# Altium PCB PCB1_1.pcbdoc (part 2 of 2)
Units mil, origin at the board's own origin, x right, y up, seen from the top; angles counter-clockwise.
Board outline 2550 x 2850 mil, 4 copper layers (Top Layer, GND02, PWR03, Bottom Layer), stack 64.1 mil thick; 130 components, 80 nets, 440 pads, 327 vias.
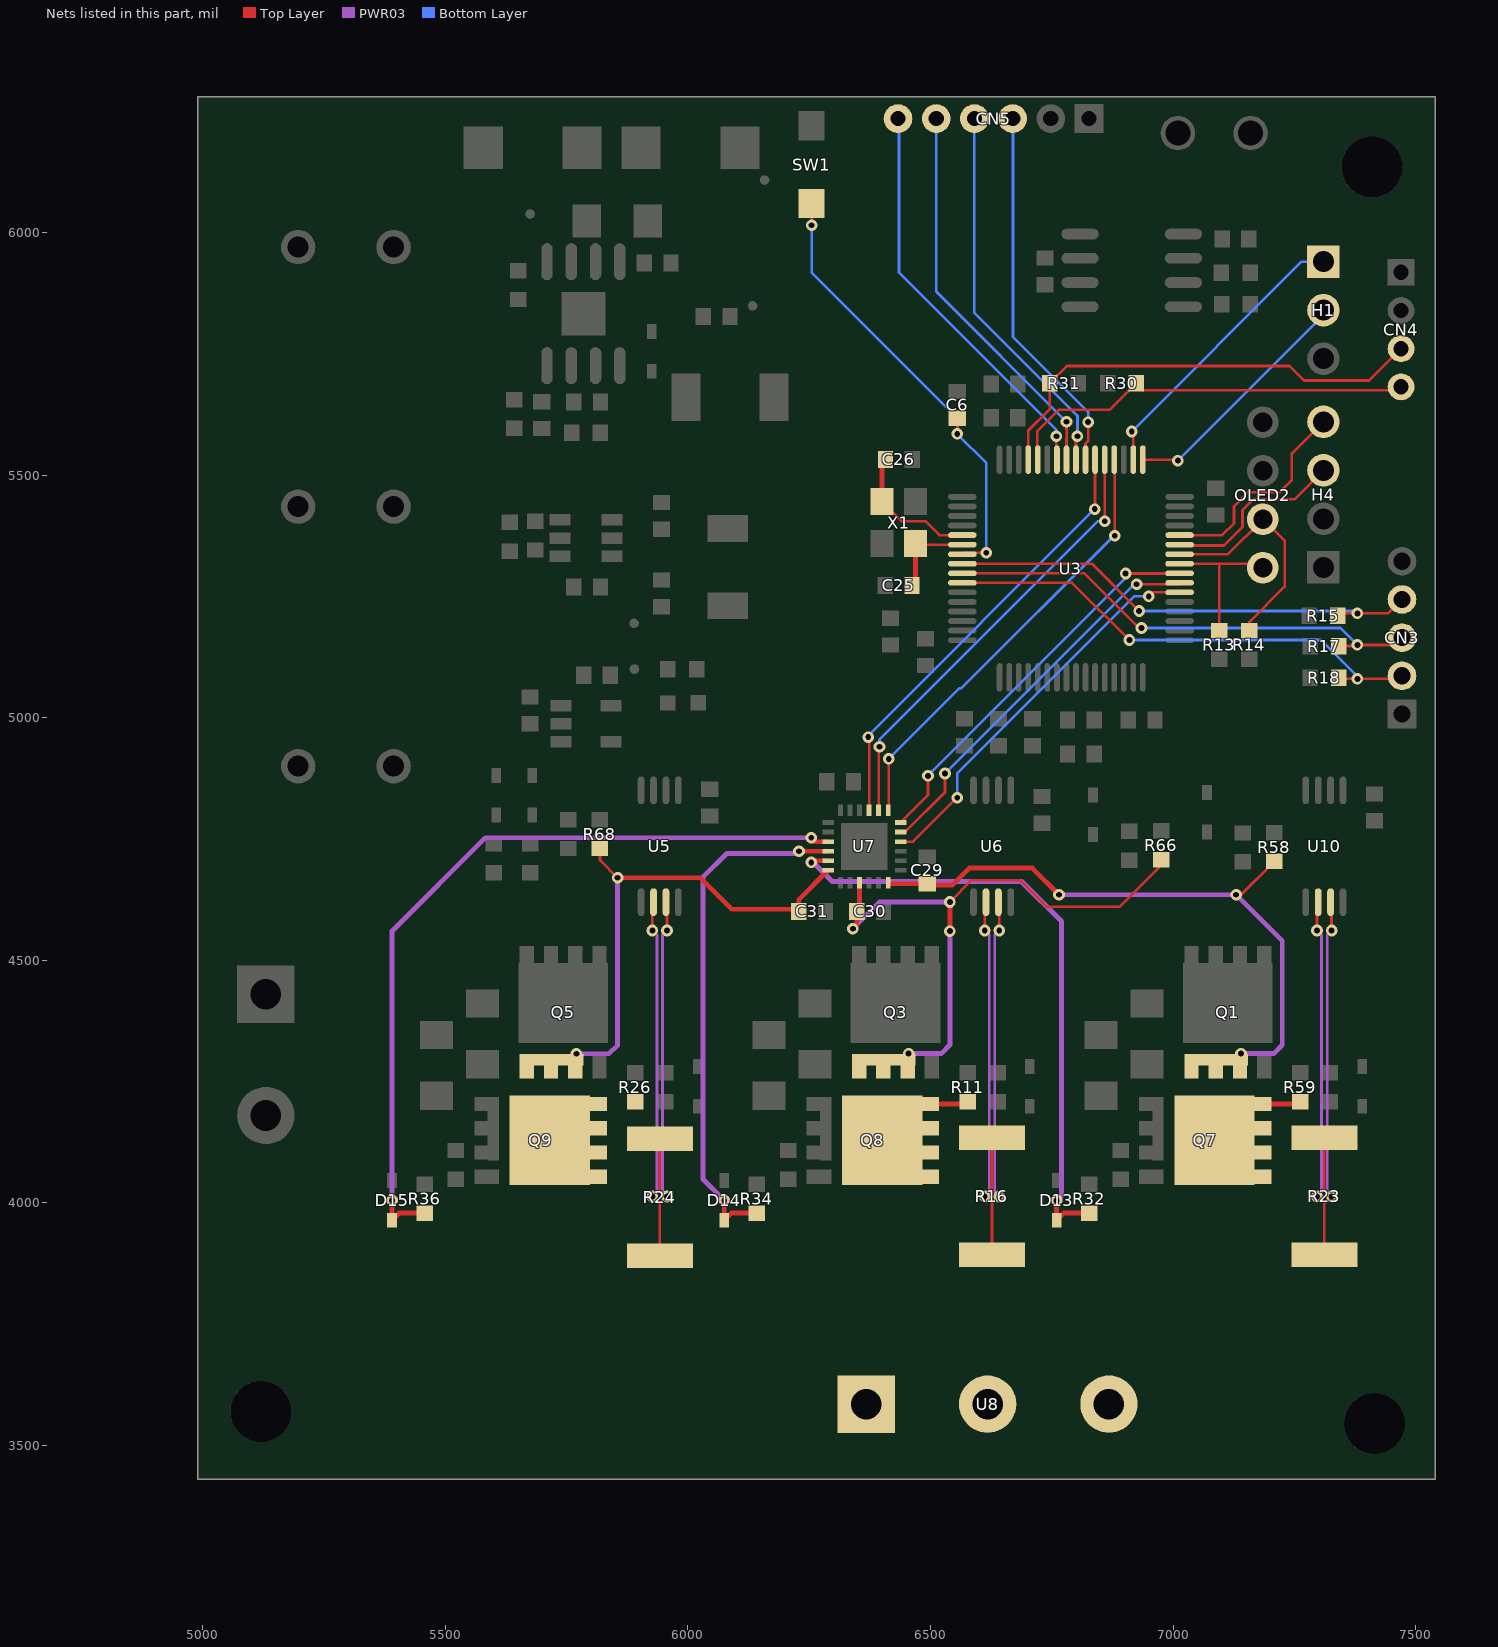
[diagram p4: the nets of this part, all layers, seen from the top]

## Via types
v1: diameter 24, hole 12, Top Layer to Bottom Layer, 327 vias

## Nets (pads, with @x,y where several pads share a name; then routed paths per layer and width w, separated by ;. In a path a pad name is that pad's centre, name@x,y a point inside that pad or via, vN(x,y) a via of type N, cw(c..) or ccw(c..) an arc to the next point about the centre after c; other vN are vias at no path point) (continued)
GLA: D13.2 R32.1 U7.11 | length 1294.7
  Top Layer w10: v1@6254.1,4704.1 6255.1,4705.1 U7.11@6288.8,4705.1 ; v1(6760,4005) D13.2@6760,3964.1 6774.7,3978.8 R32.1@6827.1,3978.8
  PWR03 w10: v1(6254.1,4701.8) 6257.9,4701.8 6297.3,4662.4 6687.6,4662.4 6770,4580 6770,4015 v1(6760,4005)
GLB: D14.2 R34.1 U7.10 | length 1078.5
  Top Layer w10: v1(6075,4005) D14.2@6075,3964.1 6089.7,3978.8 R34.1@6142.1,3978.8 ; v1(6229.1,4724.8) U7.10@6288.8,4724.8
  PWR03 w10: v1(6075,4005) 6030.9,4049.1 6030.9,4670.9 6080,4720 6224.3,4720 v1(6229.1,4724.8)
GLC: D15.2 R36.1 U7.9 | length 1650.9
  Top Layer w10: v1(5390,4005) D15.2@5390,3964.1 5404.7,3978.8 R36.1@5457.1,3978.8 ; v1(6254.1,4752.4) 6262,4744.4 U7.9@6288.8,4744.4
  PWR03 w10: v1(5390,4005) 5390,4560 5582.4,4752.4 v1(6254.1,4752.4)
I2C1_SCL_Encoder&BOOT0: CN4.3 R31.1 U3.61 | length 49.9
  Top Layer w5.5: R31.1@6745.7,5689.7 6781,5725
I2C1_SCL_ENCODER&BOOT0:  | length 904.7
  Top Layer w5.5: 6701.5,5531.9 6701.5,5591.5 6745.7,5635.7 6745.7,5689.7 ; 6781,5725 7240,5725 7270,5695 7404.4,5695 7470,5760.6
I2C1_SDA_Encoder: CN4.4 R30.1 U3.60
I2C1_SDA_ENCODER:  | length 858.9
  Top Layer w5.5: 6721.2,5531.9 6720,5533.1 6720,5590 6765,5635 6869.7,5635 6924.3,5689.7 6939,5675 7463.1,5675 7470,5681.9
I2C3_SCL_OLED: OLED2.3 R14.1 U3.42 | length 479.8
  Top Layer w5.5: U3.42@7013.6,5337 7113.1,5337 OLED2.3@7185.1,5409 7186,5409 7230,5365 7230,5270 7157.4,5197.4 R14.1@7157.4,5179.7
I2C3_SDA_OLED: OLED2.4 R13.1 U3.41 | length 313.2
  Top Layer w5.5: U3.41@7013.6,5317.3 7093.5,5317.3 ; R13.1@7095,5179.7 7095,5315.9 7093.5,5317.3 ; OLED2.4@7185.1,5309 7176.7,5317.3 7093.5,5317.3
IA+: C29.1 Q1.1 Q1.2 Q1.3 Q7.5 Q7.6 Q7.7 Q7.8 R23.1 R58.2 R59.1 U7.18 U10.2 | length 2133.8
  Top Layer w5.5: v1(7130,4635) 7140,4635 R58.2@7208.7,4703.7 ; v1(7296.8,4013.1) 7311.8,4028.1 R23.1@7311.8,4133.8 ; v1(7296.8,4561.4) 7296.8,4617.3 U10.2@7299.2,4619.8
  Top Layer w10: U7.18@6412.8,4659.8 6414.9,4657.8 C29.1@6493.3,4657.8 6496.1,4655 6545,4655 6580,4690 6710,4690 v1(6765,4635) ; Q7.8@7177.2,4203.7 7257,4203.7 R59.1@7261.8,4208.4
  PWR03 w5.5: v1(7296.8,4013.1) 7306.1,4022.5 7306.1,4552.1 v1(7296.8,4561.4)
  PWR03 w10: v1(6765,4635) v1(7130,4635) 7225,4540 7225,4325.2 7207.2,4307.5 v1(7140,4307.5)
IA-: R23.2 U8.3 U10.3 | length 742.1
  Top Layer w5.5: R23.2@7311.8,3892.4 7311.8,3998.1 v1(7326.8,4013.1) ; U10.3@7324.8,4619.8 7326.8,4617.8 v1(7326.8,4561.4)
  PWR03 w5.5: v1(7326.8,4013.1) 7317.6,4022.2 7317.6,4552.3 v1(7326.8,4561.4)
IB+: C30.2 Q3.1 Q3.2 Q3.3 Q8.5 Q8.6 Q8.7 Q8.8 R11.1 R16.1 R66.2 U6.2 U7.15 | length 2063.1
  Top Layer w5.5: v1(6540,4620) 6585,4665 6685,4665 6740,4610 6890,4610 6975.2,4695.2 R66.2@6975.2,4707.1 ; v1(6611.8,4013.1) 6626.8,4028.1 R16.1@6626.8,4133.8 ; v1(6611.8,4561.4) 6611.8,4617.1 U6.2@6614.4,4619.8
  Top Layer w10: v1(6340,4565) 6348.1,4573.1 C30.2@6348.1,4600.5 6353.8,4606.2 U7.15@6353.8,4659.8 ; Q8.8@6492.2,4203.7 6572,4203.7 R11.1@6576.8,4208.4 ; v1(6540,4560) v1(6540,4620)
  PWR03 w5.5: v1(6611.8,4013.1) 6621.1,4022.5 6621.1,4552.1 v1(6611.8,4561.4)
  PWR03 w10: v1(6340,4565) 6395,4620 v1(6540,4620) ; v1(6455,4307.5) 6522.2,4307.5 6540,4325.2 v1(6540,4560)
IB-: R16.2 U6.3 U8.2 | length 742
  Top Layer w5.5: R16.2@6626.8,3892.4 6626.8,3998.1 v1(6641.8,4013.1) ; U6.3@6640,4619.8 6641.8,4618 v1(6641.8,4561.4)
  PWR03 w5.5: v1(6641.8,4013.1) 6632.6,4022.2 6632.6,4552.3 v1(6641.8,4561.4)
IC+: C31.2 Q5.1 Q5.2 Q5.3 Q9.5 Q9.6 Q9.7 Q9.8 R24.1 R26.1 R68.2 U5.2 U7.12 | length 1767
  Top Layer w5.5: R68.2@5818.7,4730.3 5818.7,4706.3 v1(5855,4670) ; v1(5926.8,4013.1) 5941.8,4028.1 R24.1@5941.8,4133.8 ; v1(5926.8,4561.4) 5926.8,4617.4 U5.2@5929.1,4619.8
  Top Layer w10: v1(5855,4670) 6025,4670 6090,4605 6223.8,4605 C31.2@6228.3,4600.5 6228.3,4624.9 U7.12@6288.8,4685.4
  PWR03 w5.5: v1(5926.8,4013.1) 5936.1,4022.5 5936.1,4552.1 v1(5926.8,4561.4)
  PWR03 w10: v1(5770,4307.2) 5837.2,4307.2 5855,4325 v1(5855,4670)
IC-: R24.2 U5.3 U8.1 | length 742.2
  Top Layer w5.5: R24.2@5941.8,3892.4 5941.8,3998.1 v1(5956.8,4013.1) ; U5.3@5954.7,4619.8 5956.8,4617.7 v1(5956.8,4561.4)
  PWR03 w5.5: v1(5956.8,4013.1) 5947.6,4022.2 5947.6,4552.3 v1(5956.8,4561.4)
INHA: U3.38 U7.22 | length 817.4
  Top Layer w5.5: U7.22@6438.4,4744.4 6464.4,4744.4 v1(6555,4835) ; v1(6950,5250) 6958.3,5258.3 U3.38@7013.6,5258.3
  Bottom Layer w5.5: v1(6555,4835) 6555,4885 6920,5250 v1(6950,5250)
INHB: U3.39 U7.23 | length 810.7
  Top Layer w5.5: U7.23@6438.4,4764.1 6447.8,4764.1 6530,4846.3 v1(6530,4885) ; v1(6925,5275) 7010.6,5275 U3.39@7013.6,5278
  Bottom Layer w5.5: v1(6530,4885) 6920,5275 v1(6925,5275)
INHC: U3.40 U7.24 | length 817.1
  Top Layer w5.5: U7.24@6438.4,4783.8 6495,4840.4 v1(6495,4880) ; v1(6902.2,5297.2) 7013.1,5297.2 U3.40@7013.6,5297.7
  Bottom Layer w5.5: v1(6495,4880) 6495,4880.7 6902.2,5287.9 v1(6902.2,5297.2)
INLA: U3.52 U7.1 | length 920.2
  Top Layer w5.5: U7.1@6412.8,4809.4 6413.9,4810.5 v1(6413.9,4915) ; U3.52@6878.7,5531.9 6880,5530.6 v1(6880,5375)
  Bottom Layer w5.5: v1(6413.9,4915) 6559.6,5060.8 6563.6,5060.8 6877.8,5375 v1(6880,5375)
INLB: U3.53 U7.2 | length 924.1
  Top Layer w5.5: U7.2@6393.2,4809.4 6393.2,4938.2 v1(6395,4940) ; U3.53@6859,5531.9 6859.3,5531.7 v1(6859.3,5405)
  Bottom Layer w5.5: v1(6395,4940) 6395,4955 6845,5405 v1(6859.3,5405)
INLC: U3.54 U7.3 | length 916.8
  Top Layer w5.5: v1(6371.8,4960) 6373.5,4958.3 U7.3@6373.5,4809.4 ; v1(6838.5,5430) 6839.3,5430.8 U3.54@6839.3,5531.9
  Bottom Layer w5.5: v1(6371.8,4960) 6371.8,4963.2 v1(6838.5,5430)
PF0-OSC_IN: C26.1 U3.5 X1.1 | length 283.2
  Top Layer w5.5: X1.1@6400.4,5444.6 6440,5405 6490,5405 6518.6,5376.4 U3.5@6565.7,5376.4
  Top Layer w10: X1.1@6400.4,5445.6 6400.4,5525.6 C26.1@6407.2,5532.5
PF1-OSC_OUT: C25.2 U3.6 X1.3 | length 186.9
  Top Layer w5.5: X1.3@6469.3,5359 6471.5,5356.7 U3.6@6565.7,5356.7
  Top Layer w10: C25.2@6462.1,5272.5 6469.3,5279.7 X1.3@6469.3,5359
PG10-NRST: C6.2 SW1.2 U3.7 | length 952.1
  Top Layer w5.5: v1(6255,6015) SW1.2@6255,6060.1 ; v1(6555,5585) C6.2@6555,5617.4 ; U3.7@6565.7,5337 6568.8,5340.1 v1(6615,5340.1)
  Bottom Layer w5.5: v1(6255,6015) 6255,5917.6 6555,5617.6 v1(6555,5585) 6615,5525 v1(6615,5340.1)
SPI1_CS_Encoder: CN5.3 U3.55 | length 689.9
  Bottom Layer w5.5: CN5.3@6670,6235 6670,5785 6825,5630 v1(6825,5609.3)
SPI1_CS_ENCODER:  | length 79.6
  Top Layer w5.5: 6819.6,5531.9 6819.6,5565 6825,5570.4 6825,5609.3
SPI1_MISO_Encoder: CN5.5 U3.57 | length 458
  Top Layer w5.5: U3.57@6780.3,5531.9 6780.3,5575.9 6780.7,5576.4 6780.7,5593.6 6780.3,5594.1 v1(6780.3,5610)
  Bottom Layer w5.5: 6511.9,5878.4 v1(6780.3,5610)
SPI1_MISO_ENCODER:  | length 356.6
  Bottom Layer w5.5: 6511.9,5878.4 6511.9,6235
SPI1_MOSI_Encoder: CN5.6 U3.58 | length 48.6
  Top Layer w5.5: v1(6759.5,5580) 6759.5,5533 U3.58@6760.6,5531.9
SPI1_MOSI_ENCODER:  | length 789.4
  Bottom Layer w5.5: 6435,6235 6435,5917.9 6759.5,5593.4 6759.5,5580
SPI1_SCK_Encoder: CN5.4 U3.56 | length 792.6
  Top Layer w5.5: U3.56@6799.9,5531.9 6799.9,5577.1 v1(6802.9,5580)
  Bottom Layer w5.5: CN5.4@6590,6235 6590,5835 6802.9,5622.1 v1(6802.9,5580)
SPI1_SCK_ENCODER: 
SWCLK: H1.1 U3.50 | length 599.4
  Top Layer w5.5: v1(6915,5590) 6918.1,5586.9 U3.50@6918.1,5531.9
  Bottom Layer w5.5: v1(6915,5590) 7265,5940 H1.1@7310,5940
SWDIO: H1.2 U3.49 | length 507.4
  Top Layer w5.5: U3.49@6937.7,5531.9 7008.1,5531.9 v1(7010,5530)
  Bottom Layer w5.5: v1(7010,5530) 7310,5830 H1.2@7310,5840
TIM1_CH1_Hall_U: CN3.4 R15.1 U3.8 | length 892
  Top Layer w5.5: U3.8@6565.7,5317.3 6832.7,5317.3 v1(6930,5220) ; R15.1@7344.7,5215 v1(7380,5215)
  Bottom Layer w5.5: v1(6930,5220) 7375,5220 v1(7380,5215)
TIM1_CH1_HALL_U:  | length 110.9
  Top Layer w5.5: 7339.7,5210 7344.7,5215 ; 7380,5215 7443.2,5215 7472,5243.7
TIM1_CH2_Hall_V: CN3.3 R17.1 U3.9 | length 914.6
  Top Layer w5.5: U3.9@6565.7,5297.7 6817.3,5297.7 6930,5185 v1(6935,5185) ; R17.1@7341.8,5147.7 7377.7,5147.7 v1(7380,5150)
  Bottom Layer w5.5: v1(6935,5185) 7345,5185 v1(7380,5150)
TIM1_CH2_HALL_V:  | length 98.2
  Top Layer w5.5: 7380,5150 7457,5150 7472,5165
TIM1_CH3_Hall_W: CN3.2 R18.1 U3.10 | length 940.8
  Top Layer w5.5: U3.10@6565.7,5278 6792,5278 v1(6910,5160) ; R18.1@7341.6,5082.7 7344.3,5080 v1(7380,5080)
  Bottom Layer w5.5: v1(6910,5160) 7305,5160 v1@7385,5080
TIM1_CH3_HALL_W:  | length 89.6
  Top Layer w5.5: 7385,5080 7465.7,5080 7472,5086.3
USART1_RX: H4.4 U3.44 | length 445.9
  Top Layer w5.5: U3.44@7013.6,5376.4 7101.4,5376.4 7125.7,5400.7 7125.7,5435.7 7155,5465 7220,5465 7245,5490 7245,5545 H4.4@7310,5610
USART1_TX: H4.3 U3.43 | length 360.3
  Top Layer w5.5: U3.43@7034.9,5353.8 7036.1,5355 7105,5355 7143.1,5393.1 7143.1,5428.1 7165.2,5450.2 7250.2,5450.2 H4.3@7310,5510
pads on no net: U3.2 U3.3 U3.4 U3.11 U3.21 U3.22 U3.23 U3.24 U3.25 U3.26 U3.30 U3.33 U3.34 U3.35 U3.36 U3.37 U3.51 U3.59 U3.62 U4.4 U5.1 U6.1 U7.5 U7.7 U7.8 U7.21 U10.1 U18.5

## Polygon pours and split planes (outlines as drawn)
AGND on Bottom Layer (solid, remove dead copper, pour order 2): 4580,6575 4580,3075 8170,3075 8170,6575
AGND on Top Layer (solid, remove dead copper, pour order 2): 4495,6820 4495,4580 7725,4580 7725,6820
3.3V on PWR03 (solid, remove dead copper): 5655,4920 5835,5100 6408.7,5100 6564.6,5255.9 6564.6,5609.6 6630,5675 6925,5675 7135,5465 7135,5075 7305,4905 7465,4905 7480,4890 7480,4850 7455,4825 5694.3,4825 5655,4864.3
AGND on PWR03 (solid, remove dead copper): 8110,6275 8110,4915 7780,4585 5660,4585 5660,4865 5697,4828 7453,4828 7476.5,4851.5 7476.5,4888.5 7465,4900 7304.2,4900 7131.6,5072.7 7131.6,5468.4 6925,5675 6635,5675 6567.1,5607.1 6567.1,5258.3 6408.8,5100 5835,5100 5655.3,4920.4 5655.3,6710.3 5750,6805 8065,6805 8185,6685 8185,6350
AGND on PWR03 (solid, remove dead copper): 3000,7160 3000,4585 5660,4585 5660,7160
AGND on PWR03 (solid, remove dead copper): 5024.9,4589.9 5024.9,4034.1 5390,4034.1 5390,4589.9

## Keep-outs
PWR03:
  region: 6369.8,5312.3 6368.7,5313.4 6368.7,5492.3 6499.8,5492.3 6499.8,5312.3
  region: 6040,4655 6040,4570 6715,4570 6715,4655
Bottom Layer:
  region: 6369.8,5312.3 6368.7,5313.4 6368.7,5492.3 6499.8,5492.3 6499.8,5312.3
GND02:
  region: 5831.6,6040.7 5822.9,6040.7 5822.9,6027.2 5831.6,6027.2
  region: 5831.7,6013.8 5822.3,6013.8 5822.3,5998.7 5831.7,5998.7
  region: 6369.8,5312.3 6368.7,5313.4 6368.7,5492.3 6499.8,5492.3 6499.8,5312.3
  region: 6770.9,5594.1 6770.9,5576.4 6791.4,5576.4 6791.4,5594.1
  region: 6442.6,6274.4 6442.6,6235 6815,6235 6815,6274.4
  region: 6763.5,6274.4 6763.5,6235 6805,6235 6805,6274.4
Board Outline Layer:
  region: 6197,5763.2 5976.6,5763.2 5976.6,5558.5 6197,5558.5
  region: 5996.6,5220.7 6167.9,5220.7 6167.9,5399.9 5996.6,5399.9
  lines w10: 4990,3430 4990,6280 7540,6280 7540,3430 4990,3430

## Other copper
Top Layer:
  drawing of 467 lines, arcs and shapes, not listed
PWR03:
  region net IA+: 7304.2,4024.4 7308.1,4020.5 7307.7,4019.8 7307.6,4018.8 7307.9,4016.5 7308.5,4014.1 7308.7,4012.4 7296,4025.1 7297.8,4024.8 7300.1,4024.2 7302.5,4023.9 7303.5,4024
  region net IA-: 7315.7,4020.3 7319.6,4024.2 7320.2,4023.8 7321.2,4023.7 7323.5,4024.1 7325.8,4024.8 7327.5,4025.1 7314.8,4012.4 7315.1,4014.1 7315.7,4016.4 7316.1,4018.7 7316,4019.6
  region net IA+: 7308.1,4554 7304.2,4550.1 7303.5,4550.5 7302.5,4550.6 7300.1,4550.3 7297.8,4549.7 7296,4549.4 7308.7,4562.2 7308.5,4560.4 7307.9,4558 7307.6,4555.7 7307.7,4554.7
  region net IA-: 7319.6,4550.3 7315.7,4554.2 7316,4554.9 7316.1,4555.8 7315.7,4558.1 7315.1,4560.5 7314.8,4562.2 7327.5,4549.4 7325.8,4549.7 7323.5,4550.4 7321.2,4550.8 7320.2,4550.7
  region net IB+: 6623.1,4554 6619.2,4550.1 6618.5,4550.5 6617.5,4550.6 6615.1,4550.3 6612.8,4549.7 6611,4549.4 6623.7,4562.2 6623.5,4560.4 6622.9,4558 6622.6,4555.7 6622.7,4554.7
  region net IB-: 6630.7,4020.3 6634.6,4024.2 6635.2,4023.8 6636.2,4023.7 6638.5,4024.1 6640.8,4024.8 6642.5,4025.1 6629.8,4012.4 6630.1,4014.1 6630.7,4016.4 6631.1,4018.7 6631,4019.6
  region net IB-: 6634.6,4550.3 6630.7,4554.2 6631,4554.9 6631.1,4555.8 6630.7,4558.1 6630.1,4560.5 6629.8,4562.2 6642.5,4549.4 6640.8,4549.7 6638.5,4550.4 6636.2,4550.8 6635.2,4550.7
  region net IC+: 5938.1,4554 5934.2,4550.1 5933.5,4550.5 5932.5,4550.6 5930.1,4550.3 5927.8,4549.7 5926,4549.4 5938.7,4562.2 5938.5,4560.4 5937.9,4558 5937.6,4555.7 5937.7,4554.7
  region net IC-: 5949.6,4550.3 5945.7,4554.2 5946,4554.9 5946.1,4555.8 5945.7,4558.1 5945.1,4560.5 5944.8,4562.2 5957.5,4549.4 5955.8,4549.7 5953.5,4550.4 5951.2,4550.8 5950.2,4550.7
  region net IC+: 5934.2,4024.4 5938.1,4020.5 5937.7,4019.8 5937.6,4018.8 5937.9,4016.5 5938.5,4014.1 5938.7,4012.4 5926,4025.1 5927.8,4024.8 5930.1,4024.2 5932.5,4023.9 5933.5,4024
  region net GLC: 5385,4021.3 5395,4021.3 5395.3,4019.5 5396.3,4017.3 5397.5,4014.9 5399,4012.9 5381,4012.9 5382.5,4014.9 5383.8,4017.3 5384.7,4019.5
  region net GHC: 6048.9,4325.6 6058.9,4325.6 6059.2,4323.8 6060.1,4321.5 6061.4,4319.2 6062.9,4317.2 6044.9,4317.2 6046.3,4319.2 6047.6,4321.5 6048.5,4323.8
  region net GHC: 6270.4,4635 6265.7,4645 6266.7,4645.1 6267.9,4645.4 6270.3,4646.5 6272.5,4648 6273.4,4648.9 6274.1,4649.7 6278.8,4632.4 6276.6,4633.3 6274.2,4634.2 6272,4634.8
  region net GLB: 6217,4715 6209.8,4725 6211,4725.1 6212.3,4725.4 6214.7,4726.5 6215.9,4727.3 6216.9,4728.1 6217.7,4729 6218.2,4729.9 6225.4,4713.4 6220.9,4714.5 6218.6,4714.9
  region net GHB: 6736.1,4325.5 6746.1,4325.5 6746.4,4323.7 6747.3,4321.4 6748.6,4319.1 6750.1,4317.1 6732.1,4317.1 6733.6,4319.1 6734.8,4321.4 6735.7,4323.7
  region net GHB: 6383,4579.9 6390.1,4572.8 6389.1,4571.3 6388.1,4569.1 6387.4,4566.5 6387,4564.1 6374.2,4576.8 6376.7,4577.2 6379.3,4577.9 6381.5,4578.9
  region net GLA: 6269.5,4697.3 6265.3,4687.3 6264.5,4688 6263.5,4688.6 6261.1,4689.5 6258.5,4690 6257.2,4690 6256.1,4689.9 6265.6,4705.2 6266.4,4702.9 6267.5,4700.6 6268.6,4698.6
  region net GLB: 6059.9,4013 6067,4020.1 6068.5,4019.1 6070.7,4018.1 6073.3,4017.4 6075.8,4017 6063,4004.2 6062.6,4006.7 6061.9,4009.3 6060.9,4011.5
  region net GLA: 6766.5,4018.5 6773.5,4011.5 6773.1,4010.5 6772.6,4008.8 6772.2,4006.6 6772,4004.2 6759.2,4017 6761.6,4017.2 6763.8,4017.6 6765.5,4018.1
  region net IC+: 5786.3,4312.2 5786.3,4302.2 5784.5,4301.9 5782.3,4301 5779.9,4299.7 5777.9,4298.2 5777.9,4316.2 5779.9,4314.8 5782.3,4313.5 5784.5,4312.6
  region net IC+: 5860,4653.7 5850,4653.7 5849.7,4655.5 5848.8,4657.7 5847.5,4660.1 5846,4662.1 5864,4662.1 5862.5,4660.1 5861.3,4657.7 5860.3,4655.5
  region net IA+: 7156.3,4312.5 7156.3,4302.5 7154.5,4302.1 7152.3,4301.2 7149.9,4299.9 7147.9,4298.5 7147.9,4316.5 7149.9,4315 7152.3,4313.7 7154.5,4312.8
  region net IB+: 6471.3,4312.5 6471.3,4302.5 6469.5,4302.1 6467.3,4301.2 6464.9,4299.9 6462.9,4298.5 6462.9,4316.5 6464.9,4315 6467.3,4313.7 6469.5,4312.8
  region net IB+: 6348,4580.1 6355.1,4573 6354.1,4571.5 6353.1,4569.3 6352.4,4566.7 6352,4564.2 6339.2,4577 6341.7,4577.4 6344.3,4578.1 6346.5,4579.1
  region net IB+: 6523.7,4615 6523.7,4625 6525.5,4625.3 6527.7,4626.3 6530.1,4627.5 6532.1,4629 6532.1,4611 6530.1,4612.5 6527.7,4613.8 6525.5,4614.7
  region net IB+: 6545,4543.7 6535,4543.7 6534.7,4545.5 6533.8,4547.7 6532.5,4550.1 6531,4552.1 6549,4552.1 6547.5,4550.1 6546.3,4547.7 6545.3,4545.5
  region net GHA: 7385,4256.3 7395,4256.3 7395.3,4254.5 7396.3,4252.3 7397.5,4249.9 7399,4247.9 7381,4247.9 7382.5,4249.9 7383.8,4252.3 7384.7,4254.5
  region net GHA: 6545.7,4690 6545.1,4680 6543.4,4679.7 6541.1,4678.8 6538.8,4677.6 6536.7,4676.1 6537.3,4694.1 6539.3,4692.6 6541.6,4691.3 6543.9,4690.4
  region net IA+: 6781.3,4640 6781.3,4630 6779.5,4629.7 6777.3,4628.8 6774.9,4627.5 6772.9,4626 6772.9,4644 6774.9,4642.5 6777.3,4641.3 6779.5,4640.3
  region net GLC: 6237.8,4747.4 6237.8,4757.4 6239.6,4757.7 6241.8,4758.6 6244.2,4759.9 6246.2,4761.4 6246.2,4743.4 6244.2,4744.8 6241.8,4746.1 6239.6,4747
  region net IA+: 7113.7,4630 7113.7,4640 7115.5,4640.3 7117.7,4641.3 7120.1,4642.5 7122.1,4644 7122.1,4626 7120.1,4627.5 7117.7,4628.8 7115.5,4629.7
  region net IA+: 7145.1,4627 7138,4619.9 7136.5,4620.9 7134.3,4621.9 7131.7,4622.6 7129.2,4623 7142,4635.8 7142.4,4633.3 7143.1,4630.7 7144.1,4628.5
Bottom Layer:
  region net AGND: 5934.2,5295.2 5930.3,5299.1 5930.7,5300.3 5931.2,5302.7 5931.9,5309.5 5944.6,5296.8 5937.8,5296.1 5935.4,5295.6
  region net $1N197: 5836.1,5274.6 5836.1,5264.6 5834.3,5264.3 5832.1,5263.4 5829.7,5262.1 5827.7,5260.6 5827.7,5278.6 5829.7,5277.2 5832.1,5275.9 5834.3,5275
  region net $1N197: 5885,5356.9 5875,5356.6 5874.7,5358.5 5873.7,5360.7 5872.4,5363.1 5871,5365 5888.9,5365.3 5887.5,5363.2 5886.2,5360.9 5885.3,5358.7
  region net $1N197: 5867.9,5356.9 5865.6,5359.2 5865.6,5385.4 5890.1,5410 6070,5410 6070,5373.3 5904.7,5373.3 5888.3,5356.9
  region net 5V: 5895.9,5219.2 5897.1,5224.7 5900,5226.6 5905.5,5230.7 5904.3,5212.7 5901.8,5215.1 5899.3,5217.2 5897.2,5218.7
  region net 5V: 5651.3,5303.8 5647.4,5299.9 5646.3,5300.3 5643.8,5300.8 5637.1,5301.5 5649.8,5314.2 5650.5,5307.4 5650.9,5305
  region net AGND: 5698.1,5302.1 5692.3,5300.2 5691.2,5300.9 5690,5301.4 5688.6,5301.7 5687.2,5301.9 5684.4,5302 5682.4,5302.2 5696.9,5312.9 5696.8,5309.5 5697,5306.2 5697.4,5303.6 5697.7,5302.7
  region net 12V: 5899.8,5448.6 5903.9,5454.1 5905.2,5454.3 5906.4,5454.8 5907.6,5455.5 5908.7,5456.3 5910.8,5458 5912.3,5459.2 5908.2,5441.7 5906.1,5444.2 5903.7,5446.5 5901.5,5448 5900.5,5448.5
  region net 12V: 5768.6,5385.6 5774.1,5385.6 5774.7,5384.5 5776.1,5382.5 5780.4,5377.2 5762.4,5377.2 5766.7,5382.5 5768.1,5384.5
  region net ADC_CU: 6586.3,5042.8 6586.3,5037.3 6585.2,5036.7 6583.2,5035.3 6577.9,5031 6577.9,5049 6583.2,5044.7 6585.2,5043.3
  region net ADC_CU: 6608.7,5037.3 6608.7,5042.8 6609.8,5043.3 6611.8,5044.7 6617.1,5049 6617.1,5031 6611.8,5035.3 6609.8,5036.7
  region net ADC_AU: 6758.1,4959.7 6754.2,4955.8 6753.1,4956.2 6750.6,4956.6 6743.9,4957.3 6756.6,4970 6757.3,4963.3 6757.7,4960.8
  region net ADC_AU: 7029.8,4786.3 7033.7,4790.2 7034.8,4789.8 7037.3,4789.4 7044,4788.7 7031.3,4776 7030.6,4782.7 7030.2,4785.2
  region net $1N188: 5945,5883.7 5935,5883.7 5934.7,5885.5 5933.8,5887.7 5932.5,5890.1 5931,5892.1 5949,5892.1 5947.5,5890.1 5946.3,5887.7 5945.3,5885.5
  region net $1N188: 5902.5,5730.8 5909.6,5723.7 5908.6,5722.2 5907.6,5720 5906.9,5717.4 5906.5,5715 5893.8,5727.7 5896.2,5728.1 5898.8,5728.8 5901,5729.8
  region net 12V: 6124.2,5821.3 6126.9,5815.8 6126.2,5815.6 6125.4,5815.2 6123.2,5813.7 6120.8,5811.5 6118.5,5809 6115.8,5826.8 6117.3,5825.5 6119.4,5823.6 6120.5,5822.8 6121.7,5822 6122.9,5821.5
  region net 12V: 5711.9,5545 5700.4,5548.7 5699.5,5549.5 5698.5,5550.2 5696.3,5551.4 5694.4,5552.3 5693,5553.1 5710.5,5555.5 5709.9,5554.4 5709.6,5553.1 5709.5,5551.7 5709.6,5550.2 5709.8,5548.8 5710.3,5547.4 5711,5546.1
  region net INLA: 6868.5,5361.8 6866.3,5367.3 6868.2,5377.3 6879.2,5363 6875.8,5363.1 6872.5,5362.9 6870,5362.4 6869.1,5362.1
  region net INLA: 6423.5,4928.5 6427.4,4924.6 6427,4923.5 6426.6,4921 6425.9,4914.2 6413.1,4927 6419.9,4927.7 6422.3,4928.1
  region net INHA: 6552.3,4851.3 6557.8,4851.3 6558.3,4850.2 6559.7,4848.2 6564,4842.9 6546,4842.9 6550.3,4848.2 6551.7,4850.2
  region net INHA: 6933.7,5247.3 6933.7,5252.8 6934.8,5253.3 6936.8,5254.7 6942.1,5259 6942.1,5241 6936.8,5245.3 6934.8,5246.7
  region net INHC: 6504,4893.6 6508.4,4890.2 6508,4888.9 6507.5,4886.5 6507.2,4883.2 6507,4879.7 6493.8,4891.9 6500.6,4892.8 6503,4893.2
  region net INHC: 6901.7,5283.5 6890.8,5280.3 6891.6,5281.3 6892.2,5282.6 6892.6,5284 6892.8,5285.5 6892.9,5287 6892.7,5288.5 6892.4,5290 6891.8,5291.2 6909.4,5287.6 6908,5286.9 6905.9,5286 6903.7,5285 6902.7,5284.3
  region net INHB: 6911.3,5262.4 6911.1,5270 6911.9,5271 6912.4,5272.2 6912.8,5273.5 6913.1,5274.8 6913.4,5277.4 6913.8,5279.2 6922.2,5263.3 6919,5263.8 6915.8,5263.8 6913,5263.3 6912,5262.9
  region net INHB: 6539.6,4898.5 6543.5,4894.6 6543.1,4893.5 6542.7,4891 6542,4884.2 6529.2,4897 6536,4897.7 6538.5,4898.1
  region net INLC: 6828.9,5416.5 6825,5420.4 6825.4,5421.5 6825.9,5424 6826.6,5430.8 6839.3,5418 6832.5,5417.3 6830.1,5416.9
  region net INLC: 6378.4,4973.8 6384.8,4972.3 6384.4,4971.7 6384,4970.8 6383.6,4968.1 6383.4,4964.9 6383.7,4961.5 6368.7,4971.6 6370.7,4971.8 6373.4,4972 6374.8,4972.2 6376.2,4972.5 6377.4,4973
  region net TIM1_CH1_HALL_U: 6946.3,5222.8 6946.3,5217.3 6945.2,5216.7 6943.2,5215.3 6937.9,5211 6937.9,5229 6943.2,5224.7 6945.2,5223.3
  region net TIM1_CH1_HALL_U: 7360.6,5217.3 7368.1,5222.8 7369.4,5222.9 7370.6,5223.3 7372.9,5224.4 7375,5225.7 7376.5,5226.5 7369,5210.1 7368.3,5211.5 7367.4,5212.7 7366.4,5213.9 7365.2,5215 7364,5215.9 7362.8,5216.6 7361.7,5217.1
  region net TIM1_CH2_HALL_V: 6951.3,5187.8 6951.3,5182.3 6950.2,5181.7 6948.2,5180.3 6942.9,5176 6942.9,5194 6948.2,5189.7 6950.2,5188.3
  region net TIM1_CH2_HALL_V: 7366.5,5159.6 7370.4,5163.5 7371.5,5163.1 7374,5162.7 7380.8,5162 7368,5149.2 7367.3,5156 7366.9,5158.5
  region net TIM1_CH3_HALL_W: 6926.3,5162.8 6926.3,5157.3 6925.2,5156.7 6923.2,5155.3 6917.9,5151 6917.9,5169 6923.2,5164.7 6925.2,5163.3
  region net TIM1_CH3_HALL_W: 7367.4,5093.7 7375,5093.9 7376,5093.1 7377.2,5092.6 7378.5,5092.2 7379.8,5091.9 7382.4,5091.6 7384.2,5091.2 7368.3,5082.8 7368.8,5086 7368.8,5089.2 7368.3,5092 7367.9,5093
  region net 12V: 6314.9,4908 6322,4915.1 6323.5,4914.1 6325.7,4913.1 6328.3,4912.4 6330.8,4912 6318,4899.2 6317.6,4901.7 6316.9,4904.3 6315.9,4906.5
  region net 12V: 6195.1,5442 6188,5434.9 6186.5,5435.9 6184.3,5436.9 6181.7,5437.6 6179.2,5438 6192,5450.8 6192.4,5448.3 6193.1,5445.7 6194.1,5443.5
  region net SPI1_MOSI_ENCODER: 6756.8,5593.4 6762.3,5593.4 6762.5,5592.6 6763.1,5591.8 6765,5590.3 6767.1,5589 6768.5,5587.9 6750.5,5587.9 6752,5589 6754.1,5590.3 6756,5591.8 6756.6,5592.6
  region net SPI1_MOSI_ENCODER: 6437.8,6196.2 6432.3,6193.5 6430.5,6195.4 6426,6200.2 6412.3,6214.1 6456.5,6216.9 6454.7,6215.1 6452.1,6213 6445.8,6208 6442.8,6205.2 6440.2,6202.3 6439.2,6200.8 6438.4,6199.3 6437.9,6197.8
  region net SPI1_MISO_ENCODER: 6766.8,5619.6 6770.6,5623.5 6771.8,5623.1 6774.2,5622.7 6781,5622 6768.3,5609.3 6767.6,5616 6767.1,5618.5
  region net SPI1_MISO_ENCODER: 6514.6,6194.8 6509.1,6194.8 6509,6196.3 6508.5,6197.9 6507.7,6199.4 6506.6,6200.9 6505.4,6202.4 6504,6203.9 6500.8,6206.6 6494.4,6211.6 6491.7,6213.7 6489.7,6215.5 6534,6215.5 6532.1,6213.7 6529.4,6211.6 6522.9,6206.6 6519.8,6203.9 6518.4,6202.4 6517.1,6200.9 6516.1,6199.4 6515.3,6197.9 6514.8,6196.3
  region net SPI1_SCK_ENCODER: 6800.1,5596.3 6805.6,5596.3 6806.2,5595.2 6807.6,5593.2 6811.9,5587.9 6793.9,5587.9 6798.2,5593.2 6799.6,5595.2
  region net SPI1_SCK_ENCODER: 6592.8,6194.3 6587.3,6195.3 6587.1,6196.8 6586.6,6198.4 6585.8,6199.9 6584.8,6201.4 6583.5,6202.9 6582.1,6204.3 6579,6207.1 6572.6,6212.1 6569.9,6214.2 6568.1,6215.9 6612.4,6215 6610.4,6213.2 6607.7,6211.2 6604.5,6208.8 6601.1,6206.2 6597.9,6203.4 6596.5,6201.9 6595.3,6200.5 6594.2,6199 6593.4,6197.4 6592.9,6195.9
  region net SPI1_CS_ENCODER: 6822.3,5625.6 6827.8,5625.6 6828.3,5624.5 6829.7,5622.5 6834,5617.2 6816,5617.2 6820.3,5622.5 6821.7,5624.5
  region net SPI1_CS_ENCODER: 6672.8,6195.3 6667.3,6194.3 6667.1,6195.9 6666.6,6197.4 6665.8,6199 6664.7,6200.5 6663.5,6201.9 6662.1,6203.4 6658.9,6206.2 6655.5,6208.8 6652.3,6211.2 6649.6,6213.2 6647.6,6215 6691.9,6215.9 6690.1,6214.2 6687.4,6212.1 6681,6207.1 6677.9,6204.3 6676.5,6202.9 6675.2,6201.4 6674.2,6199.9 6673.4,6198.4 6672.9,6196.8
  region net PG10-NRST: 6612.3,5356.5 6617.8,5356.5 6618.3,5355.4 6619.7,5353.3 6624,5348.1 6606,5348.1 6610.3,5353.3 6611.7,5355.4
  region net PG10-NRST: 6568.5,5575.4 6564.6,5571.5 6563.5,5571.9 6561,5572.3 6554.2,5573 6567,5585.8 6567.7,5579 6568.1,5576.5
  region net SWDIO: 7019.6,5543.5 7023.5,5539.6 7023.1,5538.5 7022.7,5536 7022,5529.2 7009.2,5542 7016,5542.7 7018.5,5543.1
  region net SWDIO: 7288.8,5804.9 7277.4,5801.3 7277.8,5801.9 7278.1,5802.7 7278.5,5805.3 7278.7,5808.9 7278.8,5813.3 7278.6,5818.3 7278.2,5823.7 7277.7,5829.4 7276.9,5835 7319.1,5807.8 7317.9,5807.6 7316.4,5807.5 7312.8,5807.6 7304.3,5808.2 7299.8,5808.3 7297.6,5808.2 7295.5,5808 7293.6,5807.5 7291.8,5806.9 7290.2,5806
  region net SWCLK: 6924.6,5603.5 6928.5,5599.6 6928.1,5598.5 6927.7,5596 6927,5589.2 6914.2,5602 6921,5602.7 6923.5,5603.1
  region net SWCLK: 7268.3,5937.3 7268.3,5942.8 7270.7,5943 7272.9,5943.8 7274.9,5945.1 7276.5,5946.9 7276.5,5933.1 7274.9,5934.9 7272.9,5936.2 7270.7,5937 7268.3,5937.3
  region net FDCAN1_RX: 6898.3,5482.9 6903.8,5482.9 6904.4,5481.8 6905.8,5479.8 6910.1,5474.5 6892.1,5474.5 6896.4,5479.8 6897.8,5481.8
  region net FDCAN1_RX: 7155.7,5746.9 7156.1,5755 7156.9,5756 7157.5,5757.2 7158.2,5759.8 7158.5,5762.2 7159,5764 7166.7,5747.8 7165.2,5748.1 7163.6,5748.3 7160.4,5748.3 7158.9,5748.1 7157.6,5747.8 7156.5,5747.4
  region net FDCAN1_TX: 6935,5493.9 6942.6,5493.7 6942.1,5493 6941.7,5492 6941.2,5489.2 6941.2,5486 6941.7,5482.8 6925.8,5491.2 6927.6,5491.6 6930.2,5491.9 6931.5,5492.2 6932.8,5492.6 6934,5493.1
  region net FDCAN1_TX: 7222.8,5775 7217.3,5775 7217,5776.1 7216.4,5777.1 7215.6,5778.1 7214.6,5779.1 7212.5,5780.8 7211,5782.1 7229,5782.1 7227.5,5780.8 7225.4,5779.1 7224.4,5778.1 7223.6,5777.1 7223,5776.1
  region net PG10-NRST: 6552.3,5601.3 6557.8,5601.3 6558.3,5600.2 6559.7,5598.2 6564,5592.9 6546,5592.9 6550.3,5598.2 6551.7,5600.2
  region net PG10-NRST: 6257.8,5998.7 6252.3,5998.7 6251.7,5999.8 6250.3,6001.8 6246,6007.1 6264,6007.1 6259.7,6001.8 6258.3,5999.8
  region net 5V: 7440,5347.4 7447.1,5354.4 7449.6,5354 7455.8,5353.3 7473.8,5351.9 7442.5,5320.6 7441.1,5338.7 7440.5,5344.8
  region net 5V: 7212.8,5543.8 7219.9,5536.7 7219.5,5534 7218.9,5527.2 7217.5,5507 7183,5541.4 7203.3,5542.9 7210.1,5543.5
  region net 5V: 7410,5924.9 7404.6,5925.1 7399.4,5926 7394.2,5927.4 7389.2,5929.4 7384.5,5931.9 7380,5934.9 7375,5919.9 7380,5904.9 7384.5,5907.8 7389.2,5910.3 7394.2,5912.3 7399.4,5913.7 7404.6,5914.6 7410,5914.9
  region net 5V: 7427.4,5914.9 7427.4,5924.9 7430.9,5925.2 7434.2,5926.1 7437.3,5927.7 7440.1,5929.8 7442.4,5932.4 7442.4,5907.4 7440.1,5909.9 7437.3,5912 7434.2,5913.6 7430.9,5914.5 7427.4,5914.9
  region net 5V: 7340,5557.2 7345.4,5556.9 7350.6,5556 7355.8,5554.6 7360.8,5552.6 7365.5,5550.2 7370,5547.2 7375,5562.2 7370,5577.2 7365.5,5574.2 7360.8,5571.7 7355.8,5569.7 7350.6,5568.3 7345.4,5567.5 7340,5567.2
  region net 5V: 6821.9,6100 6821.6,6094.6 6820.7,6089.3 6819.3,6084.2 6817.3,6079.2 6814.8,6074.4 6811.8,6070 6811.9,6070 6826.5,6065 6841.9,6070 6841.8,6070 6838.9,6074.4 6836.4,6079.2 6834.4,6084.2 6833,6089.3 6832.1,6094.6 6831.9,6100 6821.9,6100
  region net 5V: 6831.9,6190.5 6821.9,6190.5 6821.5,6193.9 6820.6,6197.3 6819,6200.4 6816.9,6203.1 6814.4,6205.5 6839.4,6205.5 6836.8,6203.1 6834.7,6200.4 6833.1,6197.3 6832.2,6193.9 6831.9,6190.5
  region net 5V: 6781.3,6070 6781.3,6060 6779.5,6059.6 6777.2,6058.7 6774.9,6057.5 6772.9,6056 6772.9,6074 6774.9,6072.5 6777.2,6071.2 6779.5,6070.3
  region net INLB: 6392.3,4955 6397.8,4955 6398,4953.9 6398.6,4952.9 6399.4,4951.9 6400.4,4950.9 6402.5,4949.2 6404,4947.9 6386,4947.9 6387.5,4949.2 6389.6,4950.9 6390.6,4951.9 6391.4,4952.9 6392,4953.9
  region net INLB: 6845,5402.3 6845,5407.8 6845.9,5408 6846.9,5408.6 6847.8,5409.4 6848.6,5410.4 6850.1,5412.5 6851.3,5414 6851.3,5396 6850.1,5397.5 6848.6,5399.6 6847.8,5400.6 6846.9,5401.4 6845.9,5402

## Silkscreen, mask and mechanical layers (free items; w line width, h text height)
Top Silkscreen Layer:
  drawing of 13 lines, arcs and shapes, not listed
  text "GND" at 6135,6035 h39.4
  text "SPI" at 6475,5995 h120
  text "DCBUS" at 5595,5985 h39.4
  text "12V" at 6155.9,5875.3 h39.4
  text "SW" at 7070,5690 h120
  text "I2C" at 7370,5455 h120
  text "5V" at 5810,5180 h39.4
  text "3.3V" at 5785,5125 h39.4
  text "PWR" at 5945,4955 h39.4
  text "HAL" at 7208.7,4892.8 h120
  text "+" at 5005,4570 h200
  text "CBA" at 6825,3770 h120
  text "V2.1" at 5870,3485 h120
Top Solder Mask Layer:
  region: 6019.4,3906.3 6282.1,3645 6305,3645 6312.5,3637.5 6312.5,3524.1 6281.2,3524.1 5948.4,3856.8 6019.4,3856.8
  region: 6557.5,3586 6557.5,3858.3 6678.5,3858.3 6678.5,3576.3 6668.8,3586
  region: 7234.8,3910.5 7235,3858.2 7304.6,3858.5 6973.3,3527.2 6867,3527.2 6867,3648.1 6972.4,3648.1
  region: 5190.2,4490.8 5637.1,4490.8 5637.1,4448.6 5534.1,4448.6 5534.1,4383.5 5438.9,4383.5 5438.9,4370 5190.2,4370
  region: 5848.8,4490.8 6322.1,4490.8 6322.1,4448.6 6219.1,4448.6 6219.1,4383.5 6123.9,4383.5 6123.9,4370 5848.8,4370
  region: 6534.4,4490.8 7007.1,4490.8 7007.1,4448.6 6904.1,4448.6 6904.1,4383.5 6808.9,4383.5 6808.9,4370 6534.4,4370
Bottom Solder Mask Layer:
  region: 5130,4237.6 5130,4120.4 6981.8,4120.4 6981.8,4237.6

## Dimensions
4990,3000 to 7540,3000 on Document Layer
3995,3430 to 3995,6275 on Document Layer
